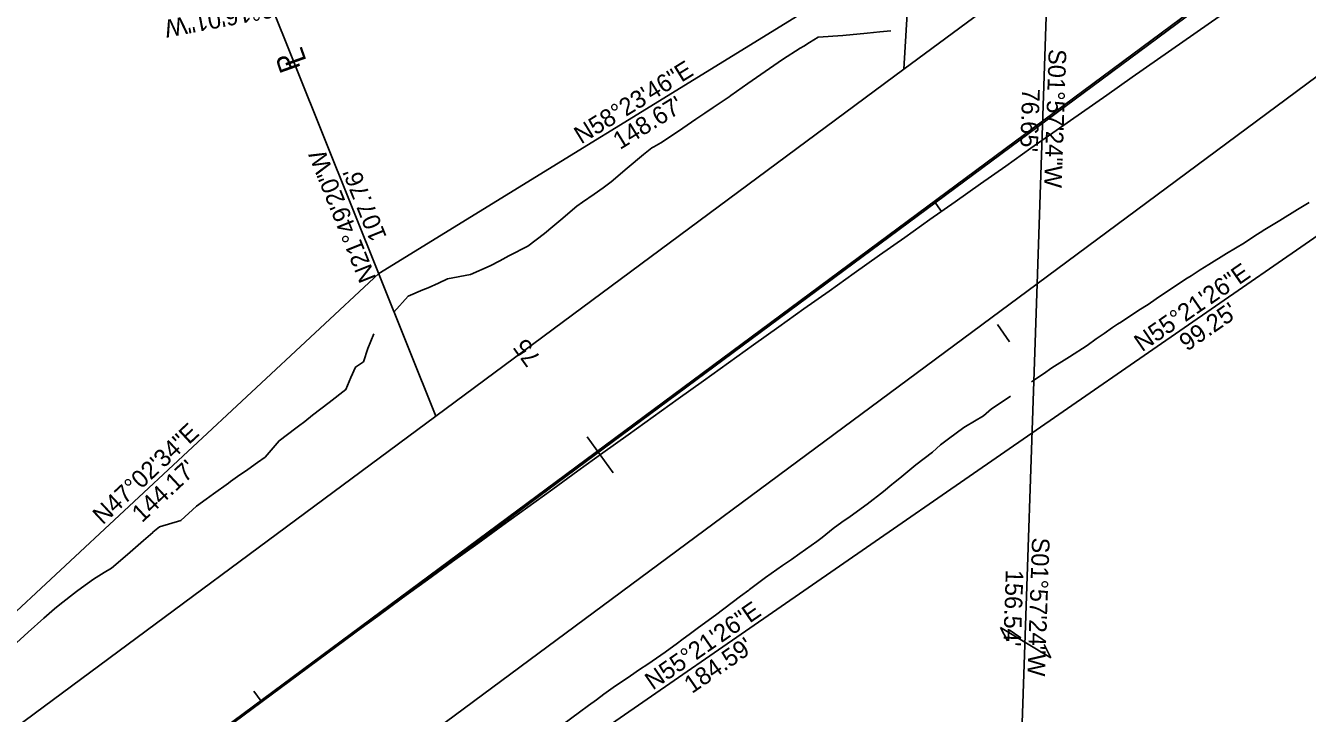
# Model space of a CAD drawing. Extents: x 1145508 to 2262867, y -3126236 to 2021677.
# Drawn here: x 1150120.6 to 1150426.5, y 2019521.4 to 2019685.5 of the extents above; entities that cross this region are included whole.
import ezdxf

# ---------------------------------------------------------------- set-up
doc = ezdxf.new("R2010")
doc.units = 0
for name, color, linetype in [('Default', 7, 'Continuous'), ('DSN_RDWY_Alignment', 7, 'Continuous'), ('DSN_RDWY_Alignment Annotation', 7, 'Continuous'), ('DSN_RDWY_Const Limits', 7, 'Continuous'), ('DSN_ROW_Annotation', 7, 'Continuous'), ('DSN_ROW_Line', 7, 'Continuous'), ('DSN_ROW_Prop-Line', 7, 'Continuous'), ('DSN_ROW_Prop-Line-Annotation', 7, 'Continuous'), ('E_Const Align', 7, 'Continuous'), ('EX_QSECTION', 7, 'Continuous'), ('EX_ROW', 7, 'Continuous'), ('EX_ROW_ANNOT', 7, 'Continuous'), ('EX_SIGN', 7, 'Continuous')]:
    doc.layers.add(name, color=color, linetype=linetype)

msp = doc.modelspace()

# ---------------------------------------------------------------- linework, layer by layer
at = {"layer": 'Default'}
msp.add_line((1150568.87, 2019814.51), (1149723.97, 2019188.76), dxfattribs=at)
at = {"layer": 'DSN_RDWY_Alignment'}
msp.add_line((1150127.35, 2019487.87), (1150506.7, 2019769.08), dxfattribs=at)
at = {"layer": 'DSN_RDWY_Alignment Annotation'}
for p, q in [((1150337.4, 2019643.6), (1150339.13, 2019641.15)), ((1150254.59, 2019587.43), (1150260.8, 2019578.81)), ((1150175.03, 2019526.75), (1150176.8, 2019524.33))]:
    msp.add_line(p, q, dxfattribs=at)
at = {"layer": 'DSN_RDWY_Const Limits'}
for points in [[(1150208.44, 2019617.16), (1150211.87, 2019620.98), (1150215.41, 2019622.47), (1150216.63, 2019622.98), (1150219.1, 2019624.03), (1150221.3, 2019625.08), (1150226.77, 2019626.09), (1150231.44, 2019628.2), (1150233.73, 2019629.4), (1150235.93, 2019630.55), (1150236.09, 2019630.64), (1150240.42, 2019632.92), (1150244.46, 2019635.9), (1150246.42, 2019637.56), (1150248.3, 2019639.16), (1150252.14, 2019642.42), (1150253.5, 2019643.34), (1150256.27, 2019645.28), (1150258.41, 2019646.78), (1150260.34, 2019648.23), (1150264.18, 2019651.5), (1150268.02, 2019654.76), (1150270.04, 2019656.34), (1150270.5, 2019656.61), (1150272.19, 2019657.56), (1150276.4, 2019660.31), (1150280.55, 2019663.14), (1150282.69, 2019664.6), (1150284.7, 2019665.97), (1150288.47, 2019668.53), (1150288.86, 2019668.79), (1150292.95, 2019671.7), (1150295.05, 2019673.15), (1150297.08, 2019674.56), (1150301.22, 2019677.41), (1150305.46, 2019680.11), (1150306.31, 2019680.62), (1150307.66, 2019681.44), (1150309.76, 2019682.73), (1150315.62, 2019683.14), (1150321.39, 2019683.66), (1150324.44, 2019683.98), (1150327.11, 2019684.26)], [(1150360.62, 2019600.51), (1150361.38, 2019601.03), (1150362.19, 2019601.58), (1150363.48, 2019602.46), (1150365.51, 2019603.82), (1150369.72, 2019606.49), (1150373.9, 2019609.2), (1150376.06, 2019610.74), (1150377.97, 2019612.07), (1150379.96, 2019613.46), (1150381.18, 2019614.28), (1150381.19, 2019614.28), (1150381.19, 2019614.29), (1150382.09, 2019614.87), (1150386.27, 2019617.58), (1150388.45, 2019619), (1150390.42, 2019620.34), (1150394.54, 2019623.13), (1150397.82, 2019625.22), (1150398.75, 2019625.81), (1150400.93, 2019627.2), (1150402.95, 2019628.49), (1150407.17, 2019631.14), (1150411.48, 2019633.67), (1150414.15, 2019635.47), (1150415.64, 2019636.4), (1150415.94, 2019636.58), (1150419.88, 2019639.03), (1150424.16, 2019641.6), (1150426.88, 2019643.3)], [(1150117.44, 2019537.4), (1150121.17, 2019540.78), (1150124.92, 2019544.16), (1150127.52, 2019546.35), (1150128.76, 2019547.41), (1150132.71, 2019550.51), (1150133.89, 2019551.39), (1150136.78, 2019553.44), (1150139.36, 2019555.06), (1150141.05, 2019556.11), (1150144.93, 2019559.3), (1150144.94, 2019559.3), (1150148.72, 2019562.64), (1150150.92, 2019564.59), (1150150.98, 2019564.63), (1150152.52, 2019565.92), (1150152.53, 2019565.93), (1150157.62, 2019567.48), (1150161.34, 2019570.9), (1150163.67, 2019572.54), (1150165.42, 2019573.83), (1150168.98, 2019576.38), (1150169.5, 2019576.75), (1150171.14, 2019577.9), (1150173.61, 2019579.64), (1150175.91, 2019581.25), (1150177.72, 2019582.52), (1150181.06, 2019586.46), (1150185.09, 2019589.45), (1150185.74, 2019589.95), (1150187.21, 2019591.08), (1150189.06, 2019592.53), (1150193.03, 2019595.62), (1150197.01, 2019598.67), (1150198.24, 2019601.54), (1150199.32, 2019604.04), (1150201.21, 2019605.33), (1150202.29, 2019608.51), (1150203.69, 2019611.97)], [(1150248.77, 2019518.79), (1150252.81, 2019521.71), (1150254.94, 2019523.3), (1150256.8, 2019524.69), (1150258.61, 2019526.05), (1150260.83, 2019527.61), (1150264.96, 2019530.39), (1150267.12, 2019531.87), (1150269.08, 2019533.2), (1150273.19, 2019536.01), (1150276.2, 2019538.18), (1150277.21, 2019538.95), (1150279.3, 2019540.5), (1150281.2, 2019541.93), (1150285.2, 2019544.9), (1150289.19, 2019547.87), (1150291.23, 2019549.4), (1150293.18, 2019550.86), (1150293.32, 2019550.97), (1150297.18, 2019553.83), (1150301.25, 2019556.7), (1150303.33, 2019558.15), (1150305.33, 2019559.55), (1150309.41, 2019562.41), (1150310.69, 2019563.41), (1150313.32, 2019565.5), (1150315.41, 2019567.01), (1150317.36, 2019568.41), (1150321.4, 2019571.32), (1150325.33, 2019574.38), (1150327.31, 2019576), (1150327.72, 2019576.33), (1150329.2, 2019577.54), (1150333.07, 2019580.69), (1150337, 2019583.75), (1150338.93, 2019585.46), (1150340.86, 2019586.92), (1150344.48, 2019589.62), (1150344.86, 2019589.89), (1150349.16, 2019592.43), (1150351.09, 2019594.09), (1150353.14, 2019595.43), (1150355.63, 2019597.12)]]:
    msp.add_lwpolyline(points, dxfattribs=at)
at = {"layer": 'DSN_ROW_Line'}
for p, q in [((1150204.85, 2019626.34), (1150331.46, 2019704.25)), ((1150360.74, 2019588.29), (1150442.39, 2019644.71)), ((1150099.33, 2019528.1), (1150204.85, 2019626.34)), ((1150208.87, 2019483.36), (1150360.74, 2019588.29))]:
    msp.add_line(p, q, dxfattribs=at)
at = {"layer": 'DSN_ROW_Prop-Line'}
for p, q in [((1150343.8, 2019909.79), (1150330.2, 2019675.08)), ((1150218.47, 2019592.32), (1150178.41, 2019692.36))]:
    msp.add_line(p, q, dxfattribs=at)
at = {"layer": 'DSN_ROW_Prop-Line-Annotation'}
for p, q in [((1150354.89, 2019538.75), (1150353.28, 2019541.91)), ((1150353.28, 2019541.91), (1150365.24, 2019534.69)), ((1150365.24, 2019534.69), (1150363.63, 2019537.85))]:
    msp.add_line(p, q, dxfattribs=at)
at = {"layer": 'E_Const Align'}
msp.add_arc((1156951.39, 2010282.18), 11459.16, 121.829445, 126.548983, dxfattribs=at)
msp.add_arc((1156951.39, 2010282.18), 11459.16, 121.829445, 126.548983, dxfattribs=at)
at = {"layer": 'EX_QSECTION'}
for p, q in [((1150364.58, 2019700.53), (1150361.96, 2019623.93)), ((1150361.96, 2019623.93), (1150356.61, 2019467.49))]:
    msp.add_line(p, q, dxfattribs=at)
at = {"layer": 'EX_ROW'}
for p, q in [((1150330.2, 2019675.08), (1150364.58, 2019700.53)), ((1150361.96, 2019623.93), (1150441.92, 2019683.15)), ((1150218.47, 2019592.32), (1150330.2, 2019675.08)), ((1150199.85, 2019503.87), (1150361.96, 2019623.93)), ((1149822.74, 2019299.24), (1150218.47, 2019592.32))]:
    msp.add_line(p, q, dxfattribs=at)
at = {"layer": 'EX_SIGN'}
msp.add_line((1150352.54, 2019614.21), (1150355.36, 2019610.06), dxfattribs=at)

# ---------------------------------------------------------------- texts
at = {"layer": 'DSN_RDWY_Alignment Annotation'}
msp.add_text('75', height=4.2, rotation=125.7418, dxfattribs=at).set_placement((1150243.72, 2019606.14))
at = {"layer": 'DSN_ROW_Annotation'}
for s, rotation, p in [('S79°16\'01"W', 190.7332, (1150185.97, 2019692.88)), ('N58°23\'46"E', 31.6038, (1150253.16, 2019657.13)), ("148.67'", 31.6038, (1150262.43, 2019655.79)), ('N21°49\'20"W', 111.8222, (1150204.32, 2019625.24)), ("107.76'", 111.8222, (1150206.84, 2019635.09)), ('N55°21\'26"E', 34.6428, (1150387.02, 2019607.55)), ("99.25'", 34.6428, (1150397.76, 2019607.67)), ('N47°02\'34"E', 42.9572, (1150138.99, 2019566.26)), ("144.17'", 42.9572, (1150148.35, 2019566.77)), ('N55°21\'26"E', 34.6428, (1150270.26, 2019526.87)), ("184.59'", 34.6428, (1150279.6, 2019526.03))]:
    msp.add_text(s, height=4.2, rotation=rotation, dxfattribs=at).set_placement(p)
at = {"layer": 'DSN_ROW_Prop-Line-Annotation'}
for s, p in [('P', (1150186.27, 2019675.38)), ('L', (1150187.68, 2019677.12))]:
    msp.add_text(s, height=5, rotation=109.5286, dxfattribs=at).set_placement(p)
at = {"layer": 'EX_ROW_ANNOT'}
for s, p in [('S01°57\'24"W', (1150364.77, 2019679.96)), ('S01°57\'24"W', (1150364.77, 2019679.96)), ("76.65'", (1150358.45, 2019670.55)), ("76.65'", (1150358.45, 2019670.55)), ('S01°57\'24"W', (1150360.79, 2019563.44)), ('S01°57\'24"W', (1150360.79, 2019563.44)), ("156.54'", (1150354.53, 2019555.74)), ("156.54'", (1150354.53, 2019555.74))]:
    msp.add_text(s, height=4.2, rotation=268.0433, dxfattribs=at).set_placement(p)

doc.saveas('drawing.dxf')
